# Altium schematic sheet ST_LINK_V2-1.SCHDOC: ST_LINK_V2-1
size A4; Date: Not used; ApprovedBy: Not used; CheckedBy: Not used; Author: Not used; CompanyName: STMicroelectronics; DrawnBy: Not used; Engineer: Not used; Organization: Not used; Address1: Not used; Address2: Not used; Address3: Not used; Address4: Not used; DocumentNumber: Not used; Revision: Not used; SheetNumber: 4; SheetTotal: 6
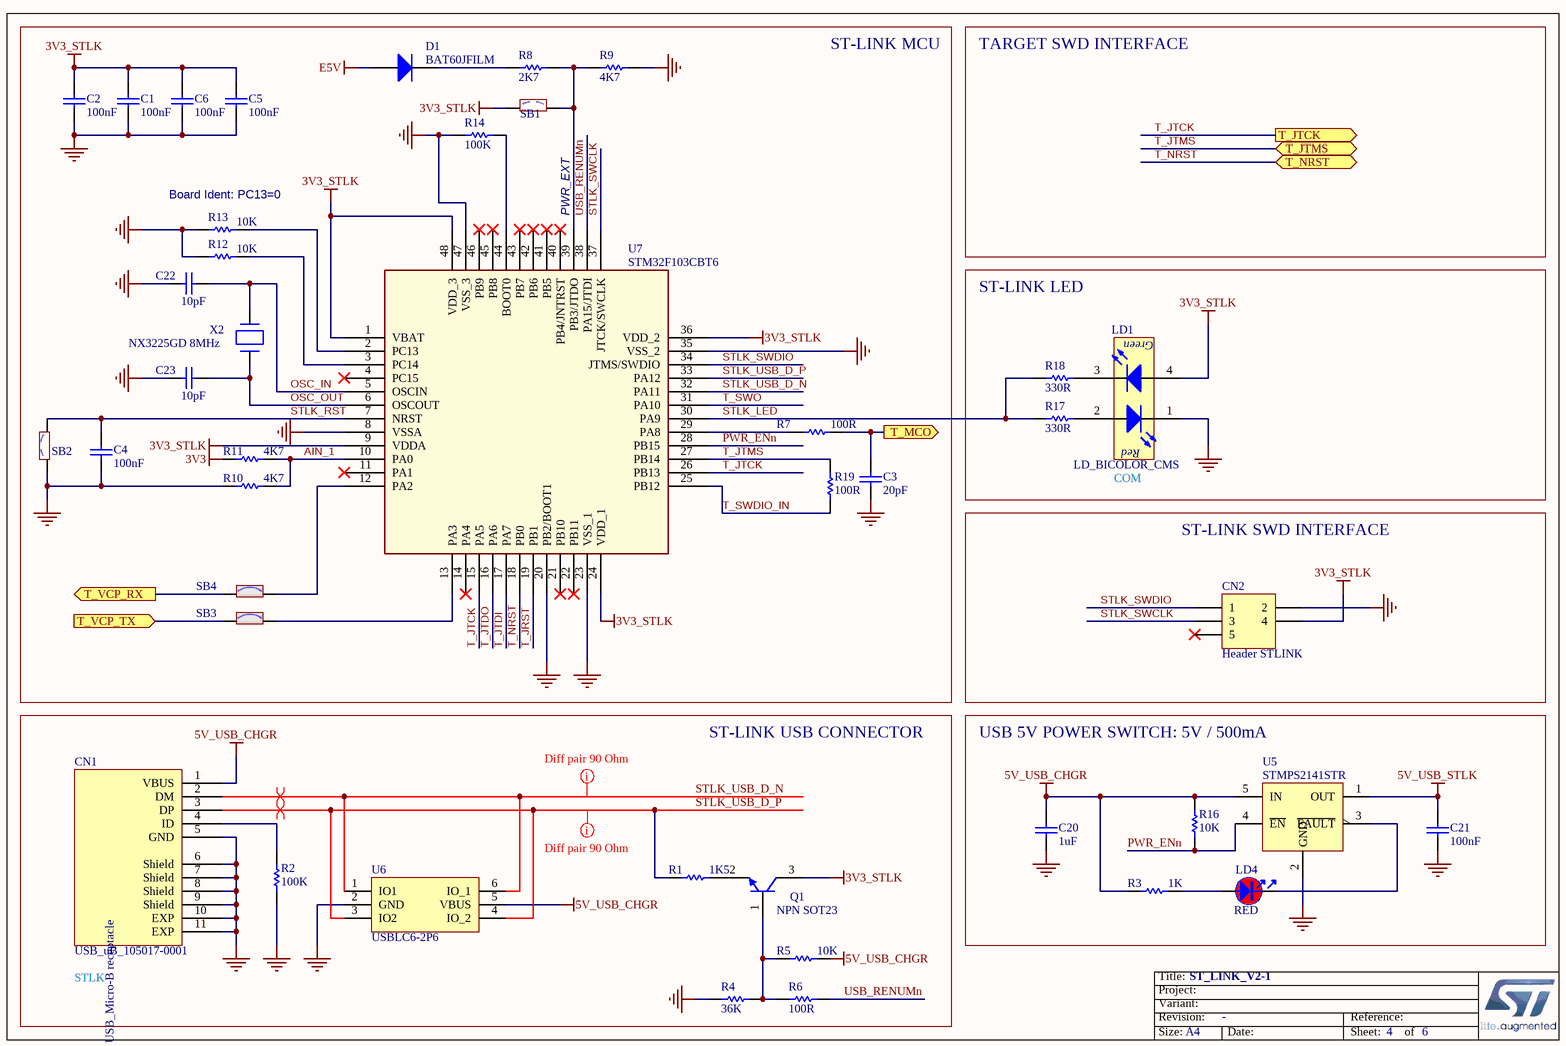
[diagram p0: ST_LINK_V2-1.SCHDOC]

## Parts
C1  value 100nF  [C0402]  (hidden comment: Capacitor)
C2  value 100nF  [C0402]  (hidden comment: Capacitor)
C3  value 20pF  [C0402]  (hidden comment: Capacitor)
C4  value 100nF  [C0402]  (hidden comment: Capacitor)
C5  value 100nF  [C0402]  (hidden comment: Capacitor)
C6  value 100nF  [C0402]  (hidden comment: Capacitor)
C20  value 1uF  [C0402]  (hidden comment: Capacitor)
C21  value 100nF  [C0402]  (hidden comment: Capacitor)
C22  value 10pF  [C0402]  (hidden comment: Capacitor)
C23  value 10pF  [C0402]  (hidden comment: Capacitor)
CN1  value USB_uB_105017-0001  [CON_USBMICROB_MOLEX_105017-0001_H2P90]  (hidden comment: USB_uB_105017.0001)
CN2  Header STLINK  [HDR_1x5_2R54_V_M]
D1  BAT60JFILM  [DIO_SOD323]
LD1  LD_BICOLOR_CMS  [LED_BI-GR_HSMF-A201-A00J1]
LD4  value RED  [LED_0603_RED_H0P4]  (hidden comment: LED_red)
Q1  value NPN SOT23  [NPN_SOT23]  (hidden comment: 9013-SOT23)
R1  value 1K5  [R0402]  (hidden comment: Resistor)
R2  value 100K  [R0402]  (hidden comment: Resistor)
R3  value 1K  [R0402]  (hidden comment: Resistor)
R4  value 36K  [R0402]  (hidden comment: Resistor)
R5  value 10K  [R0402]  (hidden comment: Resistor)
R6  value 100R  [R0402]  (hidden comment: Resistor)
R7  value 100R  [R0402]  (hidden comment: Resistor)
R8  value 2K7  [R0402]  (hidden comment: Resistor)
R9  value 4K7  [R0402]  (hidden comment: Resistor)
R10  value 4K7  [R0402]  (hidden comment: Resistor)
R11  value 4K7  [R0402]  (hidden comment: Resistor)
R12  value 10K  [R0402]  (hidden comment: Resistor)
R13  value 10K  [R0402]  (hidden comment: Resistor)
R14  value 100K  [R0402]  (hidden comment: Resistor)
R16  value 10K  [R0402]  (hidden comment: Resistor)
R17  value 330R  [R0402]  (hidden comment: Resistor)
R18  value 330R  [R0402]  (hidden comment: Resistor)
R19  value 100R  [R0402]  (hidden comment: Resistor)
SB1  SB_OFF  [SOLDER-BRIDGE_R0603-0R]  (value not drawn)
SB2  SB_OFF  [SOLDER-BRIDGE_R0603-0R]  (value not drawn)
SB3  SB_ON  [SOLDER-BRIDGE_R0603-0R]  (value not drawn)
SB4  SB_ON  [SOLDER-BRIDGE_R0603-0R]  (value not drawn)
U5  STMPS2141STR  [MOS_SOT23-5L]
U6  USBLC6-2P6  [ESD_SOT666]
U7  STM32F103CBT6  [ICC_LQFP48_7X7_P050]
X2  value NX3225GD 8MHz  [CRY_NX3225GD_2P]  (hidden comment: XTAL_2_PINS)

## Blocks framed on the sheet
ST-LINK MCU: C1-C6 C22 C23 D1 R7-R14 R19 SB1-SB4 U7 X2
ST-LINK LED: LD1 R17 R18
ST-LINK SWD INTERFACE: CN2
ST-LINK USB CONNECTOR: CN1 Q1 R1 R2 R4-R6 U6
USB 5V POWER SWITCH: 5V / 500mA: C20 C21 LD4 R3 R16 U5

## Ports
T_JTCK (out), T_JTMS (bidir), T_MCO (out), T_NRST (bidir), T_VCP_RX (out), T_VCP_TX (in)

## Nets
3V3: R11.1
3V3_STLK: C1.2 C2.2 C5.2 C6.2 CN2.4 LD1.4(YellowGreen_anode) Q1.3(C) SB1.1 U7.1(VBAT) U7.9(VDDA) U7.24(VDD_1) U7.36(VDD_2) U7.48(VDD_3)
5V_USB_CHGR: C20.2 CN1.1(VBUS) R3.1 R5.2 R16.2 U5.5(IN) U6.5(VBUS)
5V_USB_STLK: C21.2 U5.1(OUT)
E5V: D1.1(A)
GND: C1.1 C2.1 C3.1 C4.1 C5.1 C6.1 C20.1 C21.1 C22.1 C23.1 CN1.5(GND) CN1.6(Shield) CN1.7(Shield) CN1.8(Shield) CN1.9(Shield) CN1.10(EXP) CN1.11(EXP) CN2.2 LD1.1(RED_cathode) R2.1 R4.1 R9.2 R10.1 R12.1 R13.1 R14.1 SB2.1 U5.2(GND) U6.2(GND) U7.8(VSSA) U7.20(PB2/BOOT1) U7.23(VSS_1) U7.35(VSS_2) U7.47(VSS_3)
AIN_1: R10.2 R11.2 U7.10(PA0)
OSC_IN: C22.2 U7.5(OSCIN) X2.1(X1)
OSC_OUT: C23.2 U7.6(OSCOUT) X2.2(X2)
PWR_ENn: R16.1 U5.4(~{EN}) U7.28(PB15)
STLK_LED: R17.1 R18.1 U7.30(PA9)
STLK_RST: C4.2 SB2.2 U7.7(NRST)
STLK_SWCLK: CN2.3 U7.37(JTCK/SWCLK)
STLK_SWDIO: CN2.1 U7.34(JTMS/SWDIO)
STLK_USB_D_N: CN1.2(DM) U6.1(IO1) U6.6(IO_1) U7.32(PA11)
STLK_USB_D_P: CN1.3(DP) R1.1 U6.3(IO2) U6.4(IO_2) U7.33(PA12)
T_JRST: U7.19(PB1)
T_JTCK: U7.15(PA5) U7.26(PB13) ; port T_JTCK
T_JTDI: U7.17(PA7)
T_JTDO: U7.16(PA6)
T_JTMS: R19.2 U7.27(PB14) ; port T_JTMS
T_MCO: C3.2 R7.2 ; port T_MCO
T_NRST: U7.18(PB0) ; port T_NRST
T_SWDIO_IN: R19.1 U7.25(PB12)
T_SWO: U7.31(PA10)
T_VCP_RX: SB4.1 ; port T_VCP_RX
T_VCP_TX: SB3.1 ; port T_VCP_TX
USB_RENUMn: R6.2 U7.38(PA15/JTDI)
NetCN1_4: CN1.4(ID) R2.2
NetD1_2: D1.2(K) R8.1
NetLD1_2: LD1.2(Red_anode) R17.2
NetLD1_3: LD1.3(YellowGreen_cathode) R18.2
NetLD4_1: LD4.1 R3.2
NetLD4_2: LD4.2 U5.3(~{FAULT})
NetQ1_1: Q1.1(B) R4.2 R5.1 R6.1
NetQ1_2: Q1.2(E) R1.2
NetR7_1: R7.1 U7.29(PA8)
NetR8_2: R8.2 R9.1 SB1.2 U7.39(PB3/JTDO)
NetR12_2: R12.2 U7.3(PC14)
NetR13_2: R13.2 U7.2(PC13)
NetR14_2: R14.2 U7.44(BOOT0)
NetSB3_2: SB3.2 U7.13(PA3)
NetSB4_2: SB4.2 U7.12(PA2)

Not connected (* = marked no-connect by the designer): CN2 5*; U7 4(PC15)* 11(PA1)* 14(PA4)* 21(PB10)* 22(PB11)* 40(PB4/JNTRST)* 41(PB5)* 42(PB6)* 43(PB7)* 45(PB8)* 46(PB9)*

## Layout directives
differential pair: STLK_USB_D_N, STLK_USB_D_P
mark named Diff pair 90 Ohm: STLK_USB_D_N, STLK_USB_D_P

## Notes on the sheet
- TARGET SWD INTERFACE
- (near R13) Board Ident: PC13=0
- PWR_EXT
- COM
- STLK

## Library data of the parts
C1 C2 C4-C6 C21 = MCD-00102: Capacitor, MLCC, 100nF, 16V, X7R, 10%, 0402, T=0,5mm; Manufacturer_Part_Number: CC0402KRX7R7BB104; Manufacturer: YAGEO; Alternate_Manufacturer_Part_Number: GCM155R71C104KA55D; Alternate_Manufacturer: MURATA; Provided_By: SUBCO; ECCN_US: EAR99; ECCN_EU: NEC
C3 = MCD-00016: Capacitor, MLCC, 20pF, 50V, NPO, 5%, 0402, T=0,5mm; Manufacturer_Part_Number: CC0402JRNPO9BN200; Manufacturer: YAGEO; Provided_By: SUBCO; ECCN_US: EAR99; ECCN_EU: NEC
C20 = MCD-00095: Capacitor, MLCC, 1uF, 6V3, X5R, 10%, 0402, T=0,5mm; Manufacturer_Part_Number: GRM155R61E105KA12; Manufacturer: MURATA; Alternate_Manufacturer_Part_Number: GRM155R60J105KE19; Provided_By: SUBCO; ECCN_US: EAR99; ECCN_EU: NEC
C22 C23 = MCD-00015: Capacitor, MLCC, 10pF, 50V, NPO, 5%, 0402, T=0,5mm; Manufacturer_Part_Number: CC0402JRNPO9BN100; Manufacturer: YAGEO; Provided_By: SUBCO; ECCN_US: EAR99; ECCN_EU: NEC
CN1 = MCD-00028: USB-MICRO-B, 0.65mm, RA, SMT, Bottom Mount,; Part_Type: Connector; Manufacturer_Part_Number: 1050170001; Manufacturer: MOLEX; Provided_By: SUBCO
CN2 = MCD-01399: Header 5 pads for ST-LINK prog. Not fitted; Part_Type: Mechanical; Provided_By: SUBCO
D1 = MCD-00034: Manufacturer: STMICROELECTRONICS; Part_Type: Diode; BMS_Part_Number: 9151097; ECCN_US: EAR99; ECCN_EU: NEC; Provided_By: SUBCO with ST control
LD1 = MCD-00051: LED Bicolor; Part_Type: Display; Manufacturer_Part_Number: HSMF-A201-A00J1; Manufacturer: AVAGO TECHNOLOGIES; Alternate_Manufacturer_Part_Number: LE-RGW35280; Alternate_Manufacturer: EVERLUCK; ECCN_US: EAR99; ECCN_EU: NEC; Provided_By: SUBCO
LD4 = MCD-00322: LED, Red, 0603; Part_Type: Display; Manufacturer_Part_Number: 19-217/R6C-AL1M2VY/3T; Manufacturer: EVERLIGHT; ECCN_US: EAR99; ECCN_EU: NEC; Provided_By: SUBCO
Q1 = MCD-00073: NPN Bipolar Transistor; Part_Type: IC; Manufacturer_Part_Number: BSR14; Manufacturer: ON SEMICONDUCTOR; Alternate_Manufacturer_Part_Number: MMBT2222LT1G / MMBT2222ALT1G / MMBT2222ALT3G; ECCN_US: EAR99; ECCN_EU: NEC; Provided_By: SUBCO
R1 = MCD-00068: Resistor,1K5,0402,1%,1/16W; Manufacturer_Part_Number: RC0402FR-071K5L; Manufacturer: YAGEO; Provided_By: SUBCO; ECCN_US: EAR99; ECCN_EU: NEC
R2 R14 = MCD-00059: Resistor,100K,0402,1%,1/16W; Manufacturer_Part_Number: RC0402FR-07100KL; Manufacturer: YAGEO; Alternate_Manufacturer_Part_Number: RT0402FRE07100KL; Provided_By: SUBCO; ECCN_US: EAR99; ECCN_EU: NEC
R3 = MCD-00061: Resistor,1K,0402,1%,1/16W; Manufacturer_Part_Number: RC0402FR-071KL; Manufacturer: YAGEO; Provided_By: SUBCO; ECCN_US: EAR99; ECCN_EU: NEC
R4 = MCD-00069: Resistor,36K,0402,1%,1/16W; Manufacturer_Part_Number: RC0402FR-0736KL; Manufacturer: YAGEO; Provided_By: SUBCO; ECCN_US: EAR99; ECCN_EU: NEC
R5 R12 R13 R16 = MCD-00053: Resistor,10K,0402,1%,1/16W; Manufacturer_Part_Number: RC0402FR-0710KL; Manufacturer: YAGEO; Provided_By: SUBCO; ECCN_US: EAR99; ECCN_EU: NEC
R6 R7 R19 = MCD-00067: Resistor,100R,0402,1%,1/16W; Manufacturer_Part_Number: RC0402FR-07100RL; Manufacturer: YAGEO; Provided_By: SUBCO; ECCN_US: EAR99; ECCN_EU: NEC
R8 = MCD-00055: Resistor,2K7,0402,1%,1/16W; Manufacturer_Part_Number: RC0402FR-072K7L; Manufacturer: YAGEO; Provided_By: SUBCO; ECCN_US: EAR99; ECCN_EU: NEC
R9-R11 = MCD-00065: Resistor,4K7,0402,1%,1/16W; Manufacturer_Part_Number: RC0402FR-074K7L; Manufacturer: YAGEO; Alternate_Manufacturer_Part_Number: RT0402FRE074K7L; Provided_By: SUBCO; ECCN_US: EAR99; ECCN_EU: NEC
R17 R18 = MCD-00062: Resistor,330R,0402,1%,1/16W; Manufacturer_Part_Number: RC0402FR-07330RL; Manufacturer: YAGEO; Provided_By: SUBCO; ECCN_US: EAR99; ECCN_EU: NEC
SB1 SB2 = MCD-00072: Solder Bridge OFF; Part_Type: Mechanical; Manufacturer_Part_Number: RC0603JR-070RL; Manufacturer: YAGEO; Provided_By: SUBCO
SB3 SB4 = MCD-00071: Solder Bridge ON; Part_Type: Mechanical; Manufacturer_Part_Number: RC0603JR-070RL; Manufacturer: YAGEO; Provided_By: SUBCO
U5 = MCD-00083: Enhanced single channel power switches with active low enable pin; Part_Type: IC; Manufacturer: STMICROELECTRONICS; Alternate_Manufacturer_Part_Number: TPS2041C; Alternate_Manufacturer: TEXAS INSTRUMENTS; BMS_Part_Number: 9159003; ECCN_US: EAR99; ECCN_EU: NEC; Provided_By: SUBCO with ST control
U6 = MCD-00169: USB OTG FS ESD protection; Part_Type: IC; Manufacturer: STMICROELECTRONICS; BMS_Part_Number: 9151057; ECCN_US: EAR99; ECCN_EU: NEC; Provided_By: SUBCO with ST control
U7 = MCD-00085: Medium-density performance line ARM-based 32-bit MCU with 128KB Flash; Manufacturer: STMICROELECTRONICS; Part_Type: IC; BMS_Part_Number: 9175111; ECCN_US: 3A991A2; ECCN_EU: NEC; Provided_By: SUBCO with ST control
X2 = MCD-00092: Crystal 8MHz, 8pF, +-20ppm, 500ohms max,  SMD; Part_Type: Crystal_Osc; Manufacturer_Part_Number: NX3225GD 8MHz EXS00A-CG04874; Manufacturer: NDK; BMS_Part_Number: 9157029; ECCN_US: EAR99; ECCN_EU: NEC; Provided_By: SUBCO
